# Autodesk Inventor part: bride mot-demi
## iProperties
Author: Administrateur
Created: 2001-04
Part Number: bride mot-demi
Material: Par défaut
Document SubType Name: Tôlerie
Designer: Administrateur
Control State: 0
Master: False
Checked Out: False
PropertySet Name: Design Tracking Control
Shininess: 20.0
Length Units: 11269
Angle Units: 11283
Time Units: 11279
Mass Units: 11290
Length Display Precision: 3
Angle Display Precision: 2
Compacted: False
PropertySet Name: _Private Model Information
Density: 0.0
Volumn: 0.0
Area: 0.0
PropertySet Name: Model Information
